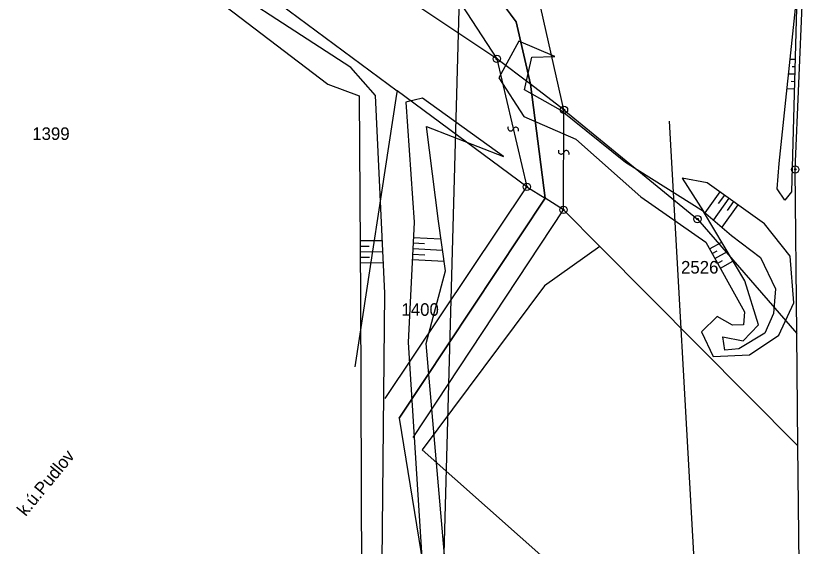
# Model space of a CAD drawing. Extents: x -469926 to -462499, y -1098642 to -1092733.
# Drawn here: x -466003.8 to -465894.9, y -1096160.3 to -1096088.5 of the extents above; entities that cross this region are included whole.
import ezdxf

# ---------------------------------------------------------------- set-up
doc = ezdxf.new("R2010")
doc.units = 0
for name, color, linetype in [('Vrstva 1', 7, 'Continuous'), ('Vrstva 12', 7, 'Continuous'), ('Vrstva 13', 7, 'Continuous'), ('Vrstva 14', 7, 'Continuous'), ('Vrstva 24', 7, 'Continuous'), ('Vrstva 4', 7, 'Continuous'), ('Vrstva 48', 7, 'Continuous'), ('Vrstva 50', 7, 'Continuous'), ('Vrstva 51', 7, 'Continuous'), ('Vrstva 55', 7, 'Continuous')]:
    doc.layers.add(name, color=color, linetype=linetype)

msp = doc.modelspace()

# ---------------------------------------------------------------- linework, layer by layer
at = {"layer": 'Vrstva 1'}
for p, q in [((-465958.52, -1096063.86), (-465938.83, -1096094.24)), ((-465938.83, -1096094.24), (-465973.15, -1096071.27)), ((-465973.77, -1096082.63), (-465952.3, -1096098.56)), ((-465898.48, -1096109.21), (-465897.35, -1096082.44)), ((-465929.75, -1096101.15), (-465933.58, -1096084.25)), ((-465934.29, -1096097.69), (-465938.83, -1096094.24)), ((-465929.75, -1096101.15), (-465934.29, -1096097.69)), ((-465952.37, -1096099.04), (-465958.01, -1096135.91)), ((-465952.3, -1096098.56), (-465952.37, -1096099.04)), ((-465934.77, -1096111.56), (-465952.3, -1096098.56)), ((-465929.75, -1096101.15), (-465911.69, -1096115.93)), ((-465898.26, -1096131.4), (-465898.48, -1096109.21)), ((-465953.92, -1096140.23), (-465934.77, -1096111.56)), ((-465934.77, -1096111.56), (-465932.29, -1096113.12)), ((-465929.82, -1096114.68), (-465932.29, -1096113.12)), ((-465950.14, -1096145.49), (-465929.82, -1096114.68)), ((-465929.82, -1096114.68), (-465924.89, -1096119.64)), ((-465911.69, -1096115.93), (-465898.26, -1096131.4)), ((-465924.89, -1096119.64), (-465932.37, -1096124.97)), ((-465924.89, -1096119.64), (-465898.11, -1096146.61)), ((-465932.37, -1096124.97), (-465948.94, -1096147.17)), ((-465898.11, -1096146.61), (-465898.26, -1096131.4)), ((-465900.46, -1096190.14), (-465948.94, -1096147.17)), ((-465897.95, -1096162.67), (-465898.11, -1096146.61))]:
    msp.add_line(p, q, dxfattribs=at)
at = {"layer": 'Vrstva 12'}
msp.add_line((-465907.04, -1096253.31), (-465915.47, -1096102.69), dxfattribs=at)
at = {"layer": 'Vrstva 13'}
for p, q in [((-465955, -1096063.54), (-465936.2, -1096089.24)), ((-465936.2, -1096089.24), (-465955, -1096063.54)), ((-465936.2, -1096089.24), (-465934.29, -1096097.69)), ((-465934.29, -1096097.69), (-465936.2, -1096089.24)), ((-465934.29, -1096097.69), (-465932.29, -1096113.12)), ((-465932.29, -1096113.12), (-465934.29, -1096097.69)), ((-465932.29, -1096113.12), (-465952.03, -1096142.86)), ((-465952.03, -1096142.86), (-465932.29, -1096113.12)), ((-465952.03, -1096142.86), (-465857.17, -1096728.32))]:
    msp.add_line(p, q, dxfattribs=at)
at = {"layer": 'Vrstva 14'}
msp.add_line((-465942.01, -1096016.92), (-465948.63, -1096257.21), dxfattribs=at)
at = {"layer": 'Vrstva 24'}
for centre, radius in [((-465938.83, -1096094.24), 0.5), ((-465938.83, -1096094.24), 0.1), ((-465929.75, -1096101.15), 0.5), ((-465929.75, -1096101.15), 0.1), ((-465898.48, -1096109.21), 0.5), ((-465898.48, -1096109.21), 0.1), ((-465934.77, -1096111.56), 0.5), ((-465934.77, -1096111.56), 0.1), ((-465929.82, -1096114.68), 0.5), ((-465929.82, -1096114.68), 0.1), ((-465911.69, -1096115.93), 0.5), ((-465911.69, -1096115.93), 0.1)]:
    msp.add_circle(centre, radius, dxfattribs=at)
at = {"layer": 'Vrstva 4'}
for p, q in [((-465938.83, -1096094.24), (-465934.77, -1096111.56)), ((-465929.82, -1096114.68), (-465929.75, -1096101.15))]:
    msp.add_line(p, q, dxfattribs=at)
at = {"layer": 'Vrstva 48'}
for points in [[(-465898.48, -1096094.33), (-465899.17, -1096094.31)], [(-465898.51, -1096095.33), (-465898.89, -1096095.32)], [(-465898.53, -1096096.33), (-465899.38, -1096096.31)], [(-465898.56, -1096097.33), (-465899.02, -1096097.32)], [(-465898.59, -1096098.33), (-465899.59, -1096098.3)], [(-465908.67, -1096112.25), (-465910.68, -1096115.08)], [(-465907.45, -1096113.12), (-465909.54, -1096116.05)], [(-465908.06, -1096112.69), (-465908.88, -1096113.84)], [(-465906.84, -1096113.56), (-465907.69, -1096114.75)], [(-465906.23, -1096113.99), (-465908.4, -1096117.03)], [(-465957.31, -1096118.84), (-465954.3, -1096118.82)], [(-465950.09, -1096118.42), (-465946.38, -1096118.61)], [(-465910.06, -1096119.94), (-465908.42, -1096119.04)], [(-465957.3, -1096119.59), (-465956.09, -1096119.58)], [(-465950.17, -1096119.91), (-465946.17, -1096120.12)], [(-465950.13, -1096119.16), (-465948.59, -1096119.24)], [(-465909.69, -1096120.6), (-465909.03, -1096120.23)], [(-465957.3, -1096120.34), (-465954.23, -1096120.32)], [(-465957.29, -1096121.09), (-465956.05, -1096121.08)], [(-465950.21, -1096120.66), (-465948.55, -1096120.75)], [(-465909.33, -1096121.26), (-465907.65, -1096120.33)], [(-465957.29, -1096121.84), (-465954.15, -1096121.82)], [(-465950.24, -1096121.41), (-465945.96, -1096121.63)], [(-465908.96, -1096121.91), (-465908.29, -1096121.53)], [(-465908.6, -1096122.57), (-465906.89, -1096121.62)]]:
    msp.add_lwpolyline(points, dxfattribs=at)
at = {"layer": 'Vrstva 51'}
for centre, radius, start, end in [((-465936.95, -1096103.62), 0.376, 153.4904, 339.8015), ((-465936.25, -1096103.87), 0.377, 332.8143, 160.4775), ((-465930.13, -1096106.77), 0.376, 153.4904, 339.8015), ((-465929.42, -1096107.03), 0.377, 332.8143, 160.4775)]:
    msp.add_arc(centre, radius, start, end, dxfattribs=at)
at = {"layer": 'Vrstva 55'}
for points in [[(-465952.67, -1096200), (-465954.47, -1096175.9), (-465953.95, -1096125.95), (-465955.25, -1096099.19), (-465958.57, -1096095.42), (-465982.06, -1096080.11), (-466000, -1096070.32)], [(-466000, -1096072.33), (-465982.44, -1096081.8), (-465961.68, -1096097.69), (-465957.44, -1096099.25), (-465957.26, -1096126.59), (-465957.07, -1096177.18), (-465956.25, -1096200)], [(-465898.25, -1096085.66), (-465898.96, -1096112.22), (-465899.88, -1096113.35), (-465900.9, -1096111.82), (-465900.67, -1096108.41), (-465898.25, -1096085.66)], [(-465930.97, -1096093.92), (-465935.87, -1096091.84), (-465938.55, -1096096.82), (-465935.16, -1096102.03), (-465928.12, -1096105.13), (-465919.33, -1096112.91), (-465910.55, -1096119.05), (-465905.33, -1096128.47), (-465905.46, -1096130.22), (-465906.97, -1096130.3), (-465909.01, -1096129.11), (-465911.14, -1096131.21), (-465909.55, -1096134.53), (-465904.65, -1096134.31), (-465900.71, -1096131.66), (-465898.65, -1096127.27), (-465899.15, -1096120.97), (-465902.63, -1096116.56), (-465910.4, -1096111.02), (-465913.78, -1096110.4), (-465910.87, -1096114.92), (-465907.1, -1096118.14), (-465903.15, -1096121.13), (-465901.16, -1096125.39), (-465901.41, -1096128.72), (-465902.58, -1096131.35), (-465906.11, -1096133.47), (-465907.98, -1096133.69), (-465908.26, -1096131.86), (-465905.51, -1096132.4), (-465903.43, -1096130.26), (-465905.3, -1096124.28), (-465910.87, -1096114.92), (-465921.42, -1096108.29), (-465930.2, -1096101.2), (-465935.1, -1096098.42), (-465934.08, -1096094.02), (-465930.97, -1096093.92)], [(-465937.9, -1096107.48), (-465948.88, -1096099.56), (-465951.14, -1096100.09), (-465949.98, -1096116.33), (-465950.83, -1096132.64), (-465948.36, -1096171.02), (-465943.22, -1096190.86), (-465944.58, -1096196.95), (-465944.09, -1096200)], [(-465941.3, -1096200), (-465941.46, -1096197.36), (-465939.82, -1096190.96), (-465945.15, -1096170.24), (-465948.39, -1096132.77), (-465945.78, -1096122.93), (-465946.71, -1096116.23), (-465948.32, -1096103.4), (-465937.9, -1096107.48)]]:
    msp.add_lwpolyline(points, dxfattribs=at)

# ---------------------------------------------------------------- texts
at = {"layer": 'Vrstva 50'}
for s, p in [('1399', (-466001.64, -1096105.22)), ('2526', (-465913.92, -1096123.3)), ('1400', (-465951.72, -1096129.02))]:
    msp.add_text(s, height=1.7, dxfattribs=at).set_placement(p)
msp.add_text('k.ú.Pudlov', height=1.7, rotation=50.7106, dxfattribs=at).set_placement((-466002.53, -1096156.26))

doc.saveas('drawing.dxf')
